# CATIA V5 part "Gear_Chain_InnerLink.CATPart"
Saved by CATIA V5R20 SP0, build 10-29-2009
Part number: Gear_Chain_InnerLink
Bounding box of the stored display mesh (mm): x -2.25 to 2.25, y -12.58 to 12.58, z -4.998 to 4.998
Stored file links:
  C:\Users\syed\Desktop\GITHUB\Advance-Smart-GPS-Electromagnetic-Brake-System\NIHAAL\Hardware\CATIA\Model_01\Part\Gear_Chain_InnerLink.CATPart
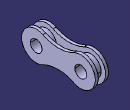
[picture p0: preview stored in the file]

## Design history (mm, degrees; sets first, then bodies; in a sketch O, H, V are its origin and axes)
Body1 (main body)
  Sketch1 on yz-plane, origin (0, 0, 0), H (0, 1, 0), V (0, 0, 1)
    construction line L1 (0, 0) -> (0, 10)
    axis line L2 (7.59, 0) -> (-7.59, 0)
    circle A1 centre (-7.59, 0) radius 3.5
    circle A2 centre (7.59, 0) radius 3.5
    circle A3 centre (-7.59, 0) radius 2
    circle A4 centre (7.59, 0) radius 2
    length L2 = 15.18
    radius A2 = 3.5
    radius A1 = 3.5
    radius A3 = 2
    radius A4 = 2
    vertical: L1 V
    horizontal: L2 H
    coincidence: L2 O
    midpoint: L2 O
  Pad1: profile Sketch1, direction (1, 0, 0), length 1.25, mirrored extent
  Sketch2 on end face of Pad1, origin (1.25, 0, 0), H (0, 1, 0), V (0, 0, 1)
    projected circle E1 centre (-7.59, 0) radius 2 from edge [end face of Pad1 | face of Pad1 from Sketch1.A3]
    projected circle E2 centre (7.59, 0) radius 2 from edge [end face of Pad1 | face of Pad1 from Sketch1.A4]
    arc A1 centre (-7.59, 0) radius 5 from (-5.3325, 4.4614) to (-5.3325, -4.4614) ccw
    point P1 (-7.59, 0)
    arc A2 centre (7.59, 0) radius 5 from (5.3325, -4.4614) to (5.3325, 4.4614) ccw
    point P2 (7.59, 0)
    arc A3 centre (0, 15) radius 11.811 from (-5.3325, 4.4614) to (5.3325, 4.4614) ccw
    point P3 (0, 15)
    point P4 (-5.3325, 4.4614)
    point P5 (5.3325, 4.4614)
    point P6 (5.3325, -4.4614)
    point P7 (-5.3325, -4.4614)
    arc A4 centre (0, -15) radius 11.811 from (-5.3325, -4.4614) to (5.3325, -4.4614) cw
    radius A2 = 5
    radius A1 = 5
    distance P3 H = 15
    concentricity: P1 E1, P2 E2
    tangency: A3 A1, A3 A2
    symmetry: P5 P6 H, P4 P7 H, A3 A4 H
  Pad2: profile Sketch2, direction (1, 0, 0), length 1
  Sketch3 on start face of Pad1, origin (-1.25, 0, 0), H (0, -1, 0), V (0, 0, 1)
    projected arc E1 centre (0, 15) radius 11.811 from (-5.3325, 4.4614) to (5.3325, 4.4614) ccw from edge [start face of Pad2 | face of Pad2 from Sketch2.A3]
    projected arc E2 centre (7.59, 0) radius 5 from (5.3325, -4.4614) to (5.3325, 4.4614) ccw from edge [start face of Pad2 | face of Pad2 from Sketch2.A1]
    projected arc E3 centre (0, -15) radius 11.811 from (5.3325, -4.4614) to (-5.3325, -4.4614) ccw from edge [start face of Pad2 | face of Pad2 from Sketch2.A4]
    projected arc E4 centre (-7.59, 0) radius 5 from (-5.3325, 4.4614) to (-5.3325, -4.4614) ccw from edge [start face of Pad2 | face of Pad2 from Sketch2.A2]
    projected circle E5 centre (-7.59, 0) radius 2 from edge [face of Pad2 | start face of Pad1]
    projected circle E6 centre (7.59, 0) radius 2 from edge [face of Pad2 | start face of Pad1]
  Pad3: profile Sketch3, direction (-1, 0, 0), length 1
